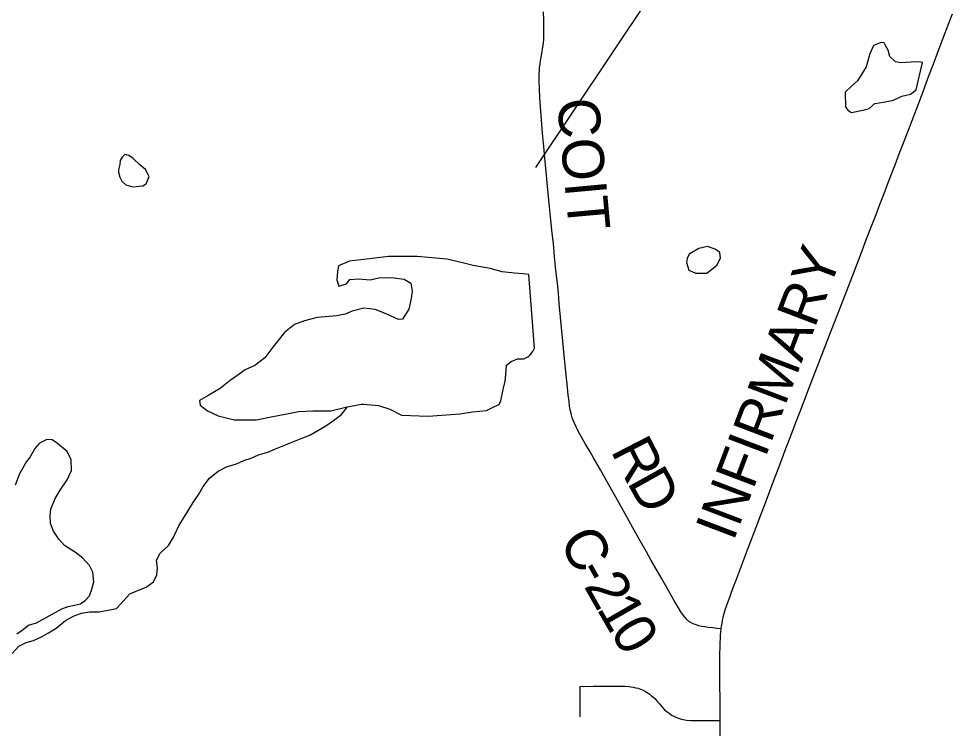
# Model space of a CAD drawing. Extents: x 0 to 34, y 0 to 22.
# Drawn here: x 14.178 to 15.455, y 14.297 to 15.268 of the extents above; entities that cross this region are included whole.
import ezdxf

# ---------------------------------------------------------------- set-up
doc = ezdxf.new("R2010")
doc.units = 0
for name, color, linetype in [('GM_X_County_Road', 7, 'Continuous'), ('GM_X_County_Road_Text', 7, 'Continuous'), ('GM_X_Minor_Lake', 7, 'Continuous'), ('GM_X_Minor_River', 7, 'Continuous'), ('GM_X_Township_Road', 7, 'Continuous')]:
    doc.layers.add(name, color=color, linetype=linetype)

msp = doc.modelspace()

# ---------------------------------------------------------------- linework, layer by layer
at = {"layer": 'GM_X_County_Road'}
for points in [[(15.1388, 14.4331), (15.1326, 14.4335), (15.1274, 14.4341), (15.121, 14.4349), (15.1163, 14.4357), (15.1124, 14.4363), (15.1083, 14.4372), (15.1046, 14.4382), (15.1006, 14.4396), (15.0972, 14.4414), (15.0946, 14.4431), (15.0913, 14.4462), (15.0871, 14.4513), (15.0834, 14.4563), (15.0803, 14.4615), (15.0754, 14.4699), (15.057, 14.5022), (15.0506, 14.5133), (15.0431, 14.5266), (15.0366, 14.5381), (15.0281, 14.5532), (15.0179, 14.5712), (15.0102, 14.5851), (14.9946, 14.6132), (14.9853, 14.63), (14.9736, 14.6505), (14.9643, 14.6667), (14.9594, 14.6751), (14.9533, 14.6854), (14.9437, 14.7027), (14.9375, 14.7153), (14.9354, 14.7204), (14.9339, 14.7259), (14.9324, 14.7325), (14.9315, 14.7378), (14.9307, 14.7439), (14.9297, 14.753), (14.9281, 14.7675), (14.9268, 14.7798), (14.9244, 14.8025), (14.9222, 14.8265), (14.9174, 14.8781), (14.9161, 14.8928), (14.9144, 14.9096), (14.9128, 14.9239), (14.9109, 14.9419), (14.9092, 14.9602), (14.9077, 14.9745), (14.9058, 14.9922), (14.9039, 15.0102), (14.902, 15.0292), (14.9007, 15.0432), (14.8992, 15.0589), (14.8976, 15.077), (14.8962, 15.0929), (14.8946, 15.1112), (14.8931, 15.1292), (14.8921, 15.1408), (14.8907, 15.1597), (14.8901, 15.1719), (14.8898, 15.1827), (14.8899, 15.1908), (14.8901, 15.1977), (14.8904, 15.2009), (14.891, 15.2056), (14.8916, 15.2103), (14.8934, 15.2203), (14.895, 15.2294), (14.8956, 15.2342), (14.896, 15.2396), (14.8962, 15.245), (14.8964, 15.2519), (14.8963, 15.259), (14.8961, 15.2663), (14.8956, 15.2773)], [(15.1388, 14.4331), (15.1393, 14.4364), (15.1399, 14.4404), (15.1406, 14.4448), (15.1414, 14.4485), (15.1425, 14.4527), (15.1443, 14.4587), (15.1461, 14.4641), (15.1482, 14.4701), (15.1504, 14.4762), (15.153, 14.4833), (15.1561, 14.4917), (15.1582, 14.4973), (15.1664, 14.519), (15.1762, 14.5447), (15.1815, 14.559), (15.1917, 14.5853), (15.2007, 14.6092), (15.2105, 14.6349), (15.219, 14.6573), (15.2274, 14.6795), (15.2339, 14.6968), (15.2399, 14.7128), (15.2466, 14.7302), (15.2583, 14.7602), (15.2652, 14.7783), (15.2792, 14.8147), (15.2884, 14.8385), (15.3032, 14.8765), (15.3156, 14.9087), (15.3291, 14.9441), (15.3377, 14.9664), (15.3453, 14.9864), (15.3505, 14.9999), (15.3562, 15.0148), (15.3616, 15.0287), (15.3682, 15.046), (15.3766, 15.0677), (15.3824, 15.0829), (15.394, 15.1128), (15.4116, 15.1597), (15.4227, 15.1894), (15.4285, 15.2047), (15.4364, 15.2257), (15.4413, 15.2387), (15.45, 15.2617), (15.4549, 15.2746)], [(15.1373, 14.3074), (15.1372, 14.3309), (15.1371, 14.3616), (15.137, 14.3811), (15.137, 14.3907), (15.1371, 14.4003), (15.1372, 14.4069), (15.1374, 14.4144), (15.1376, 14.4195), (15.1379, 14.4245), (15.1383, 14.4285), (15.1388, 14.4331)], [(15.1377, 14.2067), (15.1376, 14.2438), (15.1374, 14.2874), (15.1373, 14.3074)]]:
    msp.add_lwpolyline(points, dxfattribs=at)
at = {"layer": 'GM_X_Minor_Lake'}
for p, q in [((15.4054, 15.1705), (15.4142, 15.2077)), ((14.3161, 15.0685), (14.3146, 15.0611)), ((15.108, 14.9535), (15.0949, 14.9458)), ((14.8835, 14.8168), (14.8755, 14.918)), ((14.2025, 14.441), (14.2372, 14.4602))]:
    msp.add_line(p, q, dxfattribs=at)
for points in [[(15.4142, 15.2077), (15.4085, 15.2088), (15.3987, 15.2084), (15.385, 15.2075), (15.3771, 15.2086), (15.3695, 15.2161), (15.3671, 15.2248), (15.3637, 15.2312), (15.3617, 15.235), (15.3576, 15.2354), (15.347, 15.2311), (15.3422, 15.2197), (15.337, 15.2018), (15.325, 15.1828), (15.3168, 15.1755), (15.3085, 15.1671), (15.3087, 15.147), (15.3121, 15.1428), (15.3171, 15.1395), (15.3348, 15.143), (15.3412, 15.145), (15.3488, 15.1518), (15.3608, 15.1538), (15.3745, 15.1562), (15.3858, 15.162), (15.3975, 15.1647), (15.4054, 15.1705)], [(14.3146, 15.0611), (14.3143, 15.0578), (14.3163, 15.051), (14.3189, 15.0457), (14.3247, 15.0405), (14.3341, 15.0379), (14.3478, 15.0391), (14.3523, 15.0418), (14.3564, 15.0521), (14.3514, 15.0615), (14.3438, 15.0679), (14.3346, 15.0766), (14.3285, 15.0807), (14.3232, 15.0818), (14.3194, 15.0784), (14.3168, 15.0737), (14.3161, 15.0685)], [(15.0949, 14.9458), (15.0923, 14.9398), (15.0912, 14.9341), (15.0946, 14.9238), (15.1038, 14.9197), (15.1193, 14.9195), (15.1253, 14.9245), (15.1328, 14.9306), (15.138, 14.9401), (15.1369, 14.9477), (15.1304, 14.9526), (15.1201, 14.9559), (15.108, 14.9535)], [(14.8755, 14.918), (14.868, 14.9187), (14.8562, 14.9197), (14.8392, 14.9215), (14.8229, 14.9259), (14.7994, 14.9303), (14.785, 14.9336), (14.7637, 14.9388), (14.7228, 14.9422), (14.6838, 14.9423), (14.6612, 14.9395), (14.6305, 14.9362), (14.6154, 14.9297), (14.614, 14.9221), (14.6133, 14.9103), (14.6157, 14.9016), (14.6262, 14.9051), (14.6311, 14.9108), (14.6432, 14.9117), (14.6587, 14.9107), (14.6704, 14.913), (14.6878, 14.9135), (14.7053, 14.9114), (14.7144, 14.9058), (14.716, 14.8948), (14.7149, 14.8849), (14.7116, 14.8705), (14.7027, 14.8567), (14.6974, 14.8563), (14.6807, 14.8638), (14.6655, 14.8701), (14.6499, 14.8715), (14.6341, 14.8676), (14.6246, 14.8634), (14.6129, 14.8614), (14.5861, 14.8589), (14.5687, 14.8546), (14.5551, 14.8492), (14.5416, 14.8384), (14.5255, 14.8182), (14.5146, 14.8037), (14.501, 14.7934), (14.4875, 14.7872), (14.4765, 14.7792), (14.4671, 14.7726), (14.4536, 14.7619), (14.4381, 14.7527), (14.4253, 14.7454), (14.4261, 14.7389), (14.436, 14.7311), (14.4509, 14.7243), (14.4728, 14.7188), (14.5031, 14.7191), (14.5254, 14.7234), (14.5424, 14.7266), (14.5606, 14.7305), (14.5802, 14.731), (14.6048, 14.7312), (14.6256, 14.7363), (14.6464, 14.7402), (14.6494, 14.7403), (14.6699, 14.7385), (14.6858, 14.7337), (14.7014, 14.7255), (14.7139, 14.7248), (14.7381, 14.7239), (14.7567, 14.7255), (14.7813, 14.7269), (14.7986, 14.73), (14.8179, 14.7317), (14.8289, 14.7371), (14.8349, 14.7398), (14.8375, 14.7451), (14.8408, 14.7603), (14.8434, 14.7717), (14.8444, 14.7804), (14.8451, 14.7937), (14.8515, 14.7987), (14.8602, 14.8022), (14.8689, 14.8026), (14.8745, 14.8053), (14.8775, 14.808), (14.8813, 14.8126), (14.8835, 14.8168)], [(14.2372, 14.4602), (14.2455, 14.4637), (14.2545, 14.4653), (14.2625, 14.4669), (14.2692, 14.4722), (14.2749, 14.478), (14.2782, 14.4871), (14.2808, 14.4974), (14.2795, 14.5106), (14.2749, 14.5197), (14.2654, 14.5299), (14.2555, 14.5374), (14.2406, 14.5471), (14.233, 14.5554), (14.2254, 14.5667), (14.2215, 14.5769), (14.221, 14.5879), (14.2221, 14.5967), (14.228, 14.6111), (14.2348, 14.6226), (14.2445, 14.637), (14.2501, 14.6496), (14.2496, 14.664), (14.2442, 14.6754), (14.2309, 14.6866), (14.2236, 14.6915), (14.2164, 14.6922), (14.2066, 14.6872), (14.1999, 14.6796), (14.1935, 14.6685), (14.1887, 14.662), (14.1793, 14.6449), (14.173, 14.6297)], [(14.1753, 14.426), (14.1829, 14.431), (14.1915, 14.4379), (14.2025, 14.441)]]:
    msp.add_lwpolyline(points, dxfattribs=at)
at = {"layer": 'GM_X_Minor_River'}
msp.add_line((15.074, 15.3477), (14.8846, 15.0641), dxfattribs=at)
msp.add_lwpolyline([(14.1691, 14.399), (14.1781, 14.409), (14.1883, 14.414), (14.1981, 14.4171), (14.2091, 14.4221), (14.2189, 14.4275), (14.2294, 14.434), (14.2418, 14.4443), (14.2539, 14.4505), (14.2637, 14.4544), (14.2747, 14.4563), (14.2875, 14.4564), (14.3004, 14.4584), (14.3117, 14.4608), (14.3211, 14.4711), (14.3301, 14.4807), (14.3418, 14.4857), (14.3524, 14.4899), (14.3625, 14.4972), (14.367, 14.5067), (14.3677, 14.5162), (14.3665, 14.5268), (14.3717, 14.5364), (14.383, 14.5471), (14.3897, 14.5585), (14.3975, 14.5749), (14.4042, 14.5855), (14.4102, 14.5954), (14.4166, 14.6057), (14.4244, 14.6172), (14.4304, 14.6275), (14.439, 14.6393), (14.4507, 14.6485), (14.4624, 14.6546), (14.476, 14.6589), (14.4858, 14.6632), (14.496, 14.6663), (14.5061, 14.6709), (14.5186, 14.6748), (14.5292, 14.6794), (14.5428, 14.6845), (14.5529, 14.6887), (14.5643, 14.6933), (14.5763, 14.698), (14.5873, 14.7045), (14.5982, 14.7107), (14.6087, 14.718), (14.6193, 14.7264), (14.6278, 14.7367)], dxfattribs=at)
at = {"layer": 'GM_X_Township_Road'}
for points in [[(14.9461, 14.3123), (14.9459, 14.3153), (14.9459, 14.3279), (14.9458, 14.336), (14.946, 14.3443), (14.9459, 14.3511), (14.9461, 14.3541)], [(14.9461, 14.3541), (14.9487, 14.3543), (14.951, 14.3542), (14.9635, 14.3544), (14.9712, 14.3544), (14.9813, 14.3545), (14.9899, 14.3544), (15.0024, 14.3544), (15.0073, 14.3544), (15.0127, 14.3541), (15.0183, 14.3533), (15.0221, 14.3524), (15.0252, 14.3515), (15.0277, 14.3506), (15.032, 14.3488), (15.0353, 14.3472), (15.0412, 14.3433), (15.0436, 14.3414), (15.0452, 14.34), (15.0479, 14.3375), (15.0506, 14.3345), (15.0542, 14.3303), (15.059, 14.3247), (15.0613, 14.3223), (15.0649, 14.3194), (15.0674, 14.3173), (15.0719, 14.3145), (15.0742, 14.3133), (15.0776, 14.3116), (15.0843, 14.3094), (15.0867, 14.3088), (15.0914, 14.3079), (15.0968, 14.3075), (15.1017, 14.3074), (15.1131, 14.3073), (15.1248, 14.3074), (15.1331, 14.3074), (15.1362, 14.3074), (15.1373, 14.3074)]]:
    msp.add_lwpolyline(points, dxfattribs=at)

# ---------------------------------------------------------------- texts
at = {"layer": 'GM_X_County_Road_Text'}
for s, height, rotation, p in [('COIT', 0.05682, 275.2175, (14.9142, 15.1569)), ('INFIRMARY', 0.05682, 69.1728, (15.1554, 14.5514)), ('R', 0.0568, 297.2737, (14.987, 14.6767)), ('D', 0.0568, 299.0802, (15.0093, 14.6335)), ('C', 0.0568, 299.3746, (14.9159, 14.5526)), ('-', 0.0568, 299.4117, (14.9388, 14.5119)), ('2', 0.0568, 299.5001, (14.9503, 14.4915)), ('1', 0.0568, 299.8827, (14.9677, 14.4607)), ('0', 0.0568, 301.1303, (14.9859, 14.4292))]:
    msp.add_text(s, height=height, rotation=rotation, dxfattribs=at).set_placement(p)

doc.saveas('drawing.dxf')
